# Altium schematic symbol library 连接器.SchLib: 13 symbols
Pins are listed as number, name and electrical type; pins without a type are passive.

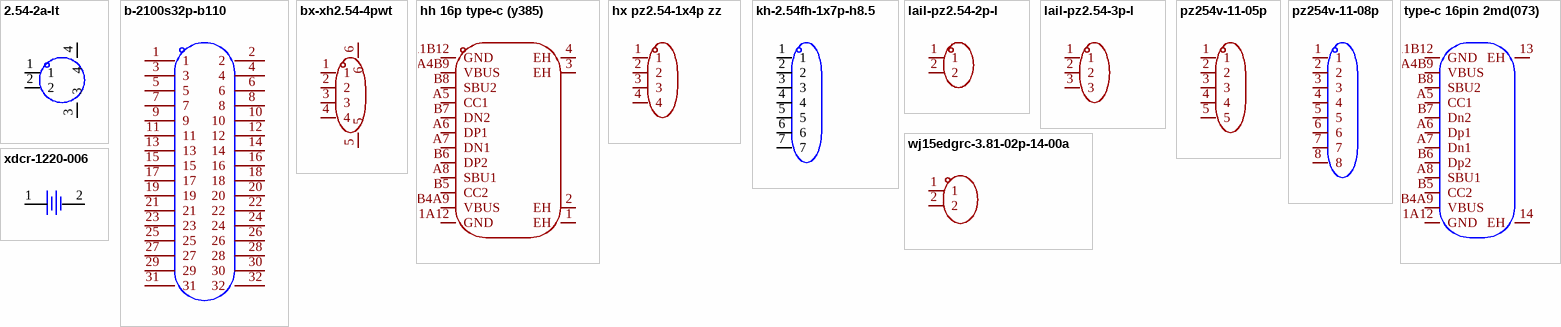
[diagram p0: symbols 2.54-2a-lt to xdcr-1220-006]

## 2.54-2a-lt
designator CN??  (value not drawn)
插针结构:1x2P;间距:2.54mm;安装方式:立贴;参考系列:XH;总PIN数:2P;排数:1;每排PIN数:2;行距:-;额定电流:500mA;触头材质:磷铜;触头镀层:锡;工作温度:-25℃~+85℃;; Manufacturer: CAX(创都); AddInBom: yes; ModelId: d8a33bf5c0154e0995c08ba39c3c8f35; ModelName: CONN-SMD_XH2.54-LS-2P; ModelTransform: 393.7,354.33,0,0,0,0,0,9.843,0; Pins Structure: 1x2P; Pitch: 2.54mm; Reference Series: XH; Number of PINs Per Row: 2; Current Rating: 500mA; Voltage Rating: 50V; Plastic Material: LCP; Z-Height of the Board: 7.9mm; Y-Width of Bottom Edge on Board: 6mm
footprint CONN-SMD_2P-P2.54_XH2.54-2AB
pins: 1, 2, 3, 4

## b-2100s32p-b110
designator H??  (value not drawn)
插针结构:2x16P;间距:2.54mm;行距:2.54mm;圆针/方针:方针;安装方式:直插;排数:双排;总PIN位数:32P;额定电流:3A;额定电压:-;配合针长度:6mm;塑高:2.54mm;端接针长度:3mm;触头材质:黄铜;触头镀层:金;工作温度:-40℃~+105℃;颜色:黑色;; Manufacturer: Ckmtw(灿科盟); Symbol: 210S-2*16P L=11.6MMGold-plated black; AddInBom: yes; ModelId: 1b51ddea29c646f89a1320d855cff4af; ModelName: HDR-TH_32P-P2.54-V-M-R2-C16-S2.54; ModelTransform: 1599.997,200,0,0,0,0,0,0,-118.11; Pin Structure: 2x16P; Pitch: 2.54mm; Circluar Pins/Square Pins: 方针; Current Rating: 3A
footprint HDR-TH_32P-P2.54-V-M-R2-C16-S2.54
pins: 1, 2, 3, 4, 5, 6, 7, 8, 9, 10, 11, 12, 13, 14, 15, 16, 17, 18, 19, 20, 21, 22, 23, 24, 25, 26, 27, 28, 29, 30, 31, 32

## bx-xh2.54-4pwt
designator U??  (value not drawn)
插针结构:1x4P;间距:2.5mm;安装方式:卧贴;参考系列:XH;总PIN数:4P;排数:1;每排PIN数:4;行距:-;额定电流:3A;触头材质:黄铜;触头镀层:锡;工作温度:-25℃~+85℃;; Manufacturer: Bossie(博锡); AddInBom: yes; ModelId: fc4292fdbd0c45d68488b12ac9a84ffb; ModelName: CONN-SMD_4P-P2.50_BX-XH2.54-4PWT; ModelTransform: 590.55,413.385,0,0,0,0,-0.003,-11.339,0; Pins Structure: 1x4P; Pitch: 2.5mm; Reference Series: XH; Number of PINs Per Row: 4; Current Rating: 3A; Voltage Rating: 250V; Supplementary Features: 辅助焊脚; Z-Height of the Board: 6.2mm; X-Length of Bottom Edge on Board (Spacing Line): 15mm; Y-Width of Bottom Edge on Board: 10.5mm
footprint CONN-SMD_4P-P2.50_BX-XH2.54-4PWT
pins: 1, 2, 3, 4, 5, 6

## hh 16p type-c (y385)
designator USB??  (value not drawn)
连接器类型:Type-C;协议标准:USB 2.0;公母:母;安装方式:卧贴;触点数量:16P;端口数量:1;额定电流 - 电源:3A;工作温度:-40℃~+85℃;; Manufacturer: HH(辉焕); AddInBom: yes; ModelId: 8525862b05ad46c6ace60b3dc3c9f97e; ModelName: USB-C-SMD_HH-16P-TYPE-C-Y385; ModelTransform: 351.9678,301.181,0,0,0,0,0,-45.275,-43.307; Protocol Standard: USB 2.0; Gender: 母; Number of Ports: 1; Current Rating-Power: 3A; Voltage Rating: 20V; Connect-Disconnect Life: 1万次; Supplementary Features: 带定位柱; Detection color: 黑色
footprint USB-C-SMD_HH-16P-TYPE-C-Y385
pins: 1 EH, 2 EH, 3 EH, 4 EH, A1B12 GND, A4B9 VBUS, A5 CC1, A6 DP1, A7 DN1, A8 SBU1, B1A12 GND, B4A9 VBUS, B5 CC2, B6 DP2, B7 DN2, B8 SBU2

## hx pz2.54-1x4p zz
designator U??  (value not drawn)
插针结构:1x4P;间距:2.54mm;行距:-;圆针/方针:方针;安装方式:直插;排数:单排;总PIN位数:4P;额定电流:3A;额定电压:1kV;配合针长度:6mm;塑高:2.5mm;端接针长度:3mm;触头材质:黄铜;触头镀层:金;工作温度:-40℃~+105℃;颜色:黑色;; Manufacturer: hanxia(韩下); AddInBom: yes; ModelId: 112f4d05e8d64e99ab9a333894bea4f9; ModelName: HDR-TH_4P-P2.54-M-LI-1X4P; ModelTransform: 399.999,104.7242,0,0,0,0,0,0,-118.11; Pin Structure: 1x4P; Pitch: 2.54mm; Circluar Pins/Square Pins: 方针; Current Rating: 3A; Voltage Rating (Max): 1kV
footprint HDR-TH_4P-P2.54-V-M
pins: 1, 2, 3, 4

## kh-2.54fh-1x7p-h8.5
designator U??  (value not drawn)
插孔结构:1x7P;间距:2.54mm;行距:-;圆孔/方孔:方孔;安装方式:直插;排数:单排;总孔位数:7P;额定电流:3A;额定电压:-;插孔方向:顶部;塑高:8.5mm;工作温度:-40℃~+105℃;; Manufacturer: kinghelm(金航标); AddInBom: yes; ModelId: 4c31987253bc43b9b52c17be2a6d3f91; ModelName: HDR-TH_7P-P2.54-F-LI-1X7P; ModelTransform: 715.7466,94.488,0,0,0,0,0,0,-118.11; Holes Structure: 1x7P; Pitch: 2.54mm; Circular Hole / Square Hole: 方孔; Number of Positions: 7P; Current Rating: 3A; Holes Direction: 顶部
footprint HDR-TH_7P-P2.54-V-F
pins: 1, 2, 3, 4, 5, 6, 7

## lail-pz2.54-2p-l
designator H??  (value not drawn)
插针结构:1x2P;间距:2.54mm;圆针/方针:方针;排数:单排;总PIN位数:2P;额定电流:3A;额定电压:250V;塑高:2.5mm;端接针长度:3mm;触头材质:黄铜;触头镀层:金;工作温度:-25℃~+80℃;颜色:黑色;; Manufacturer: 莱联; AddInBom: yes; Pin Structure: 1x2P; Pitch: 2.54mm; Circluar Pins/Square Pins: 方针; Current Rating: 3A; Voltage Rating (Max): 250V
footprint CONN-TH_LAIL-PZ2.54-2P-L
pins: 1, 2

## lail-pz2.54-3p-l
designator H??  (value not drawn)
插针结构:1x3P;间距:2.54mm;圆针/方针:方针;排数:单排;总PIN位数:3P;额定电流:3A;额定电压:250V;塑高:2.5mm;端接针长度:3mm;触头材质:黄铜;触头镀层:金;工作温度:-25℃~+80℃;颜色:黑色;; Manufacturer: LAILAN(莱联); AddInBom: yes; ModelId: 94a8ffe137b6410295cb18cd3ffd99db; ModelName: HDR-M-2.54_1x3; ModelTransform: 299.9994,100,0,0,0,0,0,0,-118.11; Pin Structure: 1x3P; Pitch: 2.54mm; Circluar Pins/Square Pins: 方针; Current Rating: 3A; Voltage Rating (Max): 250V
footprint HDR-TH_3P-P2.54-V-M-1
pins: 1, 2, 3

## pz254v-11-05p
designator H??  (value not drawn)
插针结构:1x5P;间距:2.54mm;行距:-;圆针/方针:方针;安装方式:直插;排数:单排;总PIN位数:5P;额定电流:3A;额定电压:250V;配合针长度:6mm;塑高:2.5mm;端接针长度:3mm;触头材质:黄铜;触头镀层:-;工作温度:-40℃~+105℃;颜色:黑色;; Manufacturer: XFCN(兴飞); AddInBom: yes; ModelId: 47d466e4a34f4fc5bc626cf773a24dd5; ModelName: HDR-TH_5P-P2.54-M-LI-1X5P; ModelTransform: 499.999,100,0,0,0,0,0,0,-118.11; Pin Structure: 1x5P; Pitch: 2.54mm; Circluar Pins/Square Pins: 方针; Current Rating: 3A; Voltage Rating (Max): 250V
footprint HDR-TH_5P-P2.54-V-M
pins: 1, 2, 3, 4, 5

## pz254v-11-08p
designator H??  (value not drawn)
插针结构:1x8P;间距:2.54mm;行距:-;圆针/方针:方针;安装方式:直插;排数:单排;总PIN位数:8P;额定电流:3A;额定电压:250V;配合针长度:6.1mm;塑高:2.5mm;端接针长度:3mm;触头材质:黄铜;触头镀层:金;工作温度:-40℃~+105℃;颜色:黑色;; Manufacturer: XFCN(兴飞); AddInBom: yes; ModelId: f5b96e27511e49e38545e53df2320202; ModelName: HDR-TH_8P-P2.54-V-M; ModelTransform: 807.87244,98.425,0,0,0,0,0,0,-118.11; Pin Structure: 1x8P; Pitch: 2.54mm; Circluar Pins/Square Pins: 方针; Current Rating: 3A; Voltage Rating (Max): 250V
footprint HDR-TH_8P-P2.54-V-M
pins: 1, 2, 3, 4, 5, 6, 7, 8

## type-c 16pin 2md(073)
designator USB??  (value not drawn)
连接器类型:Type-C;协议标准:-;公母:母;安装方式:卧贴;触点数量:16P;端口数量:1;额定电流 - 电源:3A;工作温度:-25℃~+85℃;; Manufacturer: SHOU HAN(首韩); AddInBom: yes; ModelId: 3a41b9ec9b654a0fad4d118405ec6290; ModelName: USB-C-SMD_TYPE-C-6PIN-2MD-073; ModelTransform: 351.9678,298.4246,0,0,0,0,0,-47.244,-35.433; Gender: 母; Number of Contacts: 16P; Number of Ports: 1; Current Rating-Power: 3A; Voltage Rating: 5V; Connect-Disconnect Life: 1万次; Detection color: 黑色
footprint USB-C-SMD_TYPE-C-16PIN-2MD-073
pins: 13 EH, 14 EH, A1B12 GND, A4B9 VBUS, A5 CC1, A6 Dp1, A7 Dn1, A8 SBU1, B1A12 GND, B4A9 VBUS, B5 CC2, B6 Dp2, B7 Dn2, B8 SBU2

## wj15edgrc-3.81-02p-14-00a
designator P??  (value not drawn)
连接器类型:板端/插座-闭口;固定方式:无固定装置;结构:1x2P;间距:3.81mm;颜色:绿色;安装方式:弯插;排数:1;每排PIN数:2;额定电流:8A;额定电压:300V;线规 - AWG:-;线规 - 平方毫米:-;工作温度:-40℃~+105℃;; Manufacturer: KANGNEX(康奈克斯电气); Symbol: WJ15EDGRC-3.81-2P; AddInBom: yes; ModelId: 816ec8aca6fe4785be70cb4c5121258d; ModelName: CONN-TH_2P_L8.5-W9.2-H7.0-P3.81; ModelTransform: 334.645,360.2355,0,0,0,0,0,-118.11,-137.795; Number of Positions or Pins: 1x2P; Pitch: 3.81mm; Number of PINs Per Row: 2; Current Rating: 8A; Voltage Rating (Max): 300V
footprint CONN-TH_2P-P3.81_WJ15EDGRC-3.81-2P
pins: 1, 2

## xdcr-1220-006
designator U??  (value not drawn)
连接器类型:电池底座;适用电池规格:CR1220;触头材质:-;触头镀层:金;工作温度:-40℃~+85℃;; Manufacturer: LX(连欣科技); AddInBom: yes; ModelId: aa69efc108b9406287881e5b236f6e7a; ModelName: BAT-SMD_CR1220-2; ModelTransform: 777.81069,586.46209,0,180,0,0,-19.685,0,-31.496; Connector Type: 电池底座; Battery Type: CR1220
footprint BAT-SMD_CR1220-2ZX
pins: 1, 2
